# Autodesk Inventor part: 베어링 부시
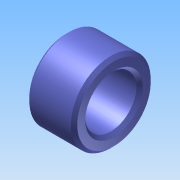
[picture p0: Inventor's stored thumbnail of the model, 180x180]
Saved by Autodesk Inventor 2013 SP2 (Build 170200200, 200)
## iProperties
Created: 2026-10
Part Number: 베어링 부시
Material: Generic
Document SubType Name: Modeling
Designer: a
Density: 1 g/cm^3
Author: a
변환 표준: STEP AP214IS
전처리기: Build: 200, Release: 2013 SP2 Update 6 - Date: Thu 07/17/2014
전송 단위: 밀리미터
불확실성: 0.01
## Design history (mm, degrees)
node "베어링 부시1"
node "솔리드1"
node "기준1"
